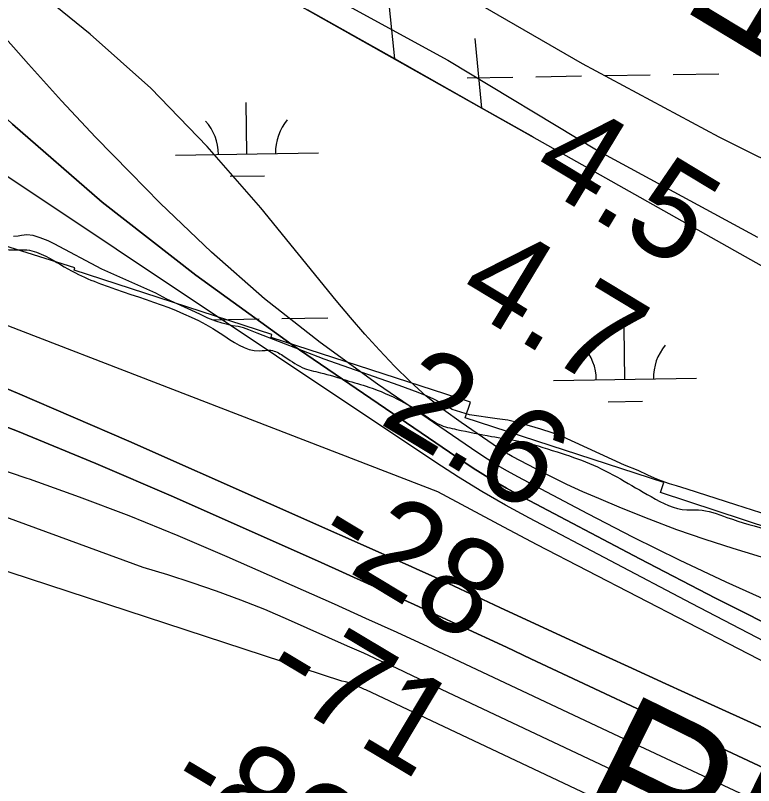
# Model space of a CAD drawing. Extents: x 3855477 to 3893699, y 299188 to 325115.
# Drawn here: x 3861858 to 3862374, y 316616 to 317154 of the extents above; entities that cross this region are included whole.
import ezdxf

# ---------------------------------------------------------------- set-up
doc = ezdxf.new("R2010")
doc.units = 0
for name, color, linetype in [('V-LEVE-TOET', 7, 'Continuous'), ('V-RIVR-EDGE', 7, 'Continuous'), ('V-RIVR-RANG', 7, 'Continuous'), ('V-RIVR-RANG-IDEN', 7, 'Continuous'), ('V-RRAP-FSHR', 7, 'Continuous'), ('V-RRAP-RVMT', 7, 'Continuous'), ('V-RRAP-RVMT-IDEN', 7, 'Continuous'), ('V-TOPO-DPTH', 7, 'Continuous'), ('V-TOPO-MAJR', 7, 'Continuous'), ('V-TOPO-MINR', 7, 'Continuous'), ('V-TOPO-WATR', 7, 'Continuous'), ('V-WETL-SWMP', 7, 'Continuous')]:
    doc.layers.add(name, color=color, linetype=linetype)

msp = doc.modelspace()

# ---------------------------------------------------------------- linework, layer by layer
at = {"layer": 'V-LEVE-TOET'}
msp.add_lwpolyline([(3862463.67, 317012.4), (3862350.14, 317069.05), (3862254.51, 317120.23), (3862173.11, 317167.56), (3862088, 317214.94), (3861990.29, 317268.78), (3861903.02, 317310.89), (3861809.48, 317359.41), (3861689.68, 317422.99), (3861660.73, 317434.38), (3861643.33, 317437.2), (3861632.74, 317435.2), (3861627.38, 317427.86), (3861628.86, 317417.8), (3861638.31, 317411.37), (3861673.53, 317394.62), (3861732.44, 317368.66), (3861791.2, 317328.42), (3861854.71, 317288.67), (3861937.17, 317241.33), (3862060.15, 317177.71), (3862160.49, 317122.79), (3862265.5, 317059.36), (3862376.89, 316999.04)], dxfattribs=at)
at = {"layer": 'V-RIVR-EDGE'}
msp.add_spline([(3861643.53, 317089.49), (3861674.18, 317073.47), (3861698.46, 317060.26), (3861723.94, 317049.04), (3861744.63, 317038.63), (3861771.7, 317026.2), (3861804.75, 317012.17), (3861824.65, 317002.96), (3861840.97, 316994.15), (3861856.1, 316990.13), (3861866.47, 316990.1), (3861879.61, 316985.69), (3861900.3, 316974.08), (3861917.82, 316966.46), (3862001.43, 316931.98), (3862028.89, 316919.56), (3862036.87, 316919.94), (3862045.23, 316916.33), (3862058.76, 316907.93), (3862071.5, 316904.31), (3862089.42, 316899.08), (3862105.35, 316894.26), (3862127.64, 316884.64), (3862144.36, 316874.64), (3862154.31, 316868.24), (3862166.65, 316864.62), (3862190.95, 316859.78), (3862210.07, 316856.54), (3862236.75, 316848.9), (3862259.45, 316840.88), (3862302.44, 316817.65), (3862327.52, 316808.43), (3862335.49, 316808.41), (3862355.41, 316803.18), (3862386.07, 316793.93), (3862408.77, 316787.5), (3862429.48, 316781.07), (3862460.14, 316771.43), (3862476.86, 316765.01), (3862487.22, 316762.2), (3862505.52, 316751), (3862525.42, 316737.4), (3862548.5, 316722.99), (3862579.14, 316706.58)], degree=3, dxfattribs=at)
at = {"layer": 'V-RRAP-FSHR'}
for p, q in [((3862123.35, 317123.63), (3862118.6, 317172.23)), ((3862184.31, 317089.24), (3862179.57, 317137.84))]:
    msp.add_line(p, q, dxfattribs=at)
for points in [[(3863755.9, 316222.32), (3863272.86, 316481.96), (3862847.86, 316733.36), (3862473.5, 316926.11), (3861935.6, 317229.54), (3861789.61, 317312.68)], [(3862123.35, 317123.63), (3862062.38, 317158.03)], [(3862184.31, 317089.24), (3862123.35, 317123.63)], [(3862220.4, 317068.89), (3862184.31, 317089.24)]]:
    msp.add_lwpolyline(points, dxfattribs=at)
at = {"layer": 'V-RRAP-RVMT'}
for p, q in [((3861899.98, 316977.66), (3861761.13, 317021.23)), ((3861899.44, 316975.94), (3861899.98, 316977.66)), ((3862037.61, 316931.1), (3861899.44, 316975.94)), ((3862037.13, 316929.01), (3862037.61, 316931.1)), ((3862176.41, 316883.79), (3862037.13, 316929.01)), ((3862172.53, 316872.81), (3862176.41, 316883.79)), ((3862311.31, 316827.52), (3862172.53, 316872.81)), ((3862309, 316820.54), (3862311.31, 316827.52)), ((3862440.97, 316777.01), (3862309, 316820.54))]:
    msp.add_line(p, q, dxfattribs=at)
at = {"layer": 'V-TOPO-DPTH'}
for points in [[(3862398.61, 316693.2), (3862222.96, 316784.06), (3862199.72, 316796.23), (3862176.56, 316808.56), (3862153.53, 316821.11), (3861655.23, 317013.53), (3861624.19, 317026.54), (3861537.43, 317064.64), (3861514.09, 317075), (3861490.8, 317085.47), (3861467.59, 317096.11), (3861444.43, 317106.87), (3861362.07, 317145.5), (3861309.75, 317169.79), (3861257.31, 317193.81), (3861204.69, 317217.42), (3861151.94, 317240.76), (3861099.14, 317263.99), (3861046.39, 317287.34), (3860993.73, 317310.87), (3860941.12, 317334.53), (3860934.1, 317337.7), (3860878.1, 317363.14)], [(3862398.61, 316693.2), (3862222.96, 316784.06), (3862199.72, 316796.23), (3862176.56, 316808.56), (3862153.53, 316821.11), (3861655.23, 317013.53), (3861624.19, 317026.54), (3861537.43, 317064.64), (3861514.09, 317075), (3861490.8, 317085.47), (3861467.59, 317096.11), (3861444.43, 317106.87), (3861362.07, 317145.5), (3861309.75, 317169.79), (3861257.31, 317193.81), (3861204.69, 317217.42), (3861151.94, 317240.76), (3861099.14, 317263.99), (3861046.39, 317287.34), (3860993.73, 317310.87), (3860941.12, 317334.53), (3860934.1, 317337.7), (3860878.1, 317363.14)], [(3861660.87, 317267.4), (3861795.55, 317134.72), (3861856.32, 317077.98), (3861918.97, 317023.54), (3861984.44, 316972.52), (3862051.79, 316923.78), (3862166.81, 316845.16), (3862178.19, 316837.66), (3862189.73, 316830.43), (3862201.51, 316823.6), (3862213.45, 316817.03), (3862294.67, 316774.12), (3862347.54, 316746.73), (3862400.7, 316719.9)], [(3861660.87, 317267.4), (3861795.55, 317134.72), (3861856.32, 317077.98), (3861918.97, 317023.54), (3861984.44, 316972.52), (3862051.79, 316923.78), (3862166.81, 316845.16), (3862178.19, 316837.66), (3862189.73, 316830.43), (3862201.51, 316823.6), (3862213.45, 316817.03), (3862294.67, 316774.12), (3862347.54, 316746.73), (3862400.7, 316719.9)], [(3862452.8, 316752.91), (3862359.91, 316781.36), (3862340.14, 316787.74), (3862320.52, 316794.51), (3862301.1, 316801.86), (3862281.83, 316809.6), (3862265.91, 316816.28), (3862254.77, 316821.12), (3862243.73, 316826.16), (3862232.82, 316831.5), (3862222.01, 316837.03), (3862205.43, 316845.79), (3862203, 316847.13), (3862200.6, 316848.52), (3862198.25, 316849.99), (3862195.93, 316851.52), (3862169.75, 316869.41), (3862157.4, 316878.42), (3862145.46, 316887.91), (3862134.12, 316898.12), (3862123.18, 316908.81), (3862112.69, 316919.98), (3862102.4, 316931.32), (3862092.39, 316942.92), (3862082.57, 316954.68), (3862029.81, 317019.5), (3861992.32, 317062.3), (3861952.93, 317103.14), (3861910.69, 317141.02), (3861866.55, 317176.93)], [(3861466.28, 317043.19), (3861624.34, 316984.23), (3861703.33, 316953.94), (3861781.92, 316922.7), (3861859.94, 316890.04), (3861937.56, 316856.42), (3862132.84, 316769.74), (3862140.89, 316766.13), (3862148.93, 316762.49), (3862156.94, 316758.8), (3862164.94, 316755.07), (3862172.93, 316751.32), (3862180.92, 316747.58), (3862188.92, 316743.86), (3862196.92, 316740.15), (3862233.64, 316723.15), (3862260.02, 316710.97), (3862286.42, 316698.83), (3862312.84, 316686.75), (3862339.28, 316674.71), (3862633.23, 316541.24)], [(3862633.23, 316541.24), (3862339.28, 316674.71), (3862312.84, 316686.75), (3862286.42, 316698.83), (3862260.02, 316710.97), (3862233.64, 316723.15), (3862196.92, 316740.15), (3862188.92, 316743.86), (3862180.92, 316747.58), (3862172.93, 316751.32), (3862164.94, 316755.07), (3862156.94, 316758.8), (3862148.93, 316762.49), (3862140.89, 316766.13), (3862132.84, 316769.74), (3861937.56, 316856.42), (3861859.94, 316890.04), (3861781.92, 316922.7), (3861703.33, 316953.94), (3861624.34, 316984.23), (3861466.28, 317043.19)], [(3861543.74, 316977.42), (3861562.28, 316970.2), (3861581.02, 316963.52), (3861599.89, 316957.2), (3861618.82, 316951.05), (3861637.72, 316944.77), (3861656.54, 316938.3), (3861675.33, 316931.69), (3861749.26, 316905.27), (3861804.73, 316884.74), (3861859.87, 316863.39), (3861914.52, 316840.81), (3861968.85, 316817.41), (3862071.98, 316771.61), (3862104.46, 316757.06), (3862136.88, 316742.37), (3862169.2, 316727.46), (3862201.45, 316712.42), (3862218.51, 316704.39), (3862259.25, 316685.24), (3862300, 316666.11), (3862340.76, 316647), (3862381.53, 316627.91)], [(3862381.53, 316627.91), (3862340.76, 316647), (3862300, 316666.11), (3862259.25, 316685.24), (3862218.51, 316704.39), (3862201.45, 316712.42), (3862169.2, 316727.46), (3862136.88, 316742.37), (3862104.46, 316757.06), (3862071.98, 316771.61), (3861968.85, 316817.41), (3861914.52, 316840.81), (3861859.87, 316863.39), (3861804.73, 316884.74), (3861749.26, 316905.27), (3861675.33, 316931.69), (3861656.54, 316938.3), (3861637.72, 316944.77), (3861618.82, 316951.05), (3861599.89, 316957.2), (3861581.02, 316963.52), (3861562.28, 316970.2), (3861543.74, 316977.42)]]:
    msp.add_lwpolyline(points, dxfattribs=at)
at = {"layer": 'V-TOPO-MAJR'}
msp.add_lwpolyline([(3862419.74, 316584.41), (3862346.04, 316618.92), (3862272.38, 316653.53), (3862168.61, 316702.42), (3862146.84, 316712.59), (3862125.02, 316722.66), (3862103.14, 316732.58), (3862081.22, 316742.41), (3862006.29, 316775.7), (3861972.18, 316790.31), (3861937.84, 316804.32), (3861903.14, 316817.4), (3861868.2, 316829.88), (3861866.7, 316830.39), (3861832.26, 316841.94), (3861797.73, 316853.19), (3861763.06, 316864.01), (3861728.29, 316874.55), (3861693.67, 316885.45), (3861659.33, 316897.13), (3861625.4, 316909.98), (3861591.76, 316923.6), (3861490.7, 316966.53)], dxfattribs=at)
at = {"layer": 'V-TOPO-MINR'}
for points in [[(3862398.61, 316693.2), (3862222.96, 316784.06), (3862199.72, 316796.23), (3862176.56, 316808.56), (3862153.53, 316821.11), (3861655.23, 317013.53), (3861624.19, 317026.54), (3861537.43, 317064.64), (3861514.09, 317075), (3861490.8, 317085.47), (3861467.59, 317096.11), (3861444.43, 317106.87), (3861362.07, 317145.5), (3861309.75, 317169.79), (3861257.31, 317193.81), (3861204.69, 317217.42), (3861151.94, 317240.76), (3861099.14, 317263.99), (3861046.39, 317287.34), (3860993.73, 317310.87), (3860941.12, 317334.53), (3860934.1, 317337.7), (3860878.1, 317363.14)], [(3862400.7, 316719.9), (3862347.54, 316746.73), (3862294.67, 316774.12), (3862213.45, 316817.03), (3862201.51, 316823.6), (3862189.73, 316830.43), (3862178.19, 316837.66), (3862166.81, 316845.16), (3862051.79, 316923.78), (3861984.44, 316972.52), (3861918.97, 317023.54), (3861856.32, 317077.98), (3861795.55, 317134.72), (3861660.87, 317267.4)], [(3862404.48, 316704.59), (3862330.72, 316742.86), (3862217.46, 316802.66), (3862200.75, 316811.81), (3862184.24, 316821.3), (3862168.03, 316831.3), (3862152.02, 316841.63), (3861817.27, 317065.08), (3861776.98, 317092.35), (3861736.94, 317119.97), (3861697.25, 317148.1), (3861657.8, 317176.57), (3861597.14, 317220.95), (3861588.02, 317227.18), (3861578.66, 317232.99), (3861568.95, 317238.17), (3861558.99, 317242.94)], [(3862387.54, 316743.16), (3862354.86, 316757.94), (3862322.4, 316773.18), (3862290.28, 316789.13), (3862258.38, 316805.55), (3862209.44, 316831.41), (3862202.26, 316835.36), (3862195.17, 316839.48), (3862188.22, 316843.83), (3862181.37, 316848.34), (3862111.27, 316896.26), (3862071.22, 316925.36), (3862032.4, 316955.91), (3861995.39, 316988.65), (3861959.6, 317022.84), (3861938.53, 317044.16), (3861914.45, 317069.03), (3861890.7, 317094.22), (3861867.47, 317119.88), (3861844.58, 317145.86), (3861821.2, 317171.27)], [(3862585.42, 316454.74), (3862103.1, 316682.52), (3862102.24, 316682.93), (3862100.5, 316683.73), (3862096.31, 316685.59), (3862093.92, 316686.57), (3862091.47, 316687.41), (3862088.98, 316688.12), (3862086.46, 316688.68), (3861390.39, 316916.73), (3861368.99, 316926.77), (3861347.62, 316936.86), (3861256.15, 316980.28), (3861194.89, 317009.08), (3861133.49, 317037.6), (3861071.9, 317065.67), (3861010.16, 317093.45), (3860959.67, 317115.96), (3860922.94, 317131.92), (3860886.02, 317147.42)], [(3862633.23, 316541.24), (3862339.28, 316674.71), (3862312.84, 316686.75), (3862286.42, 316698.83), (3862260.02, 316710.97), (3862233.64, 316723.15), (3862196.92, 316740.15), (3862188.92, 316743.86), (3862180.92, 316747.58), (3862172.93, 316751.32), (3862164.94, 316755.07), (3862156.94, 316758.8), (3862148.93, 316762.49), (3862140.89, 316766.13), (3862132.84, 316769.74), (3861937.56, 316856.42), (3861859.94, 316890.04), (3861781.92, 316922.7), (3861703.33, 316953.94), (3861624.34, 316984.23), (3861466.28, 317043.19)], [(3862381.53, 316627.91), (3862340.76, 316647), (3862300, 316666.11), (3862259.25, 316685.24), (3862218.51, 316704.39), (3862201.45, 316712.42), (3862169.2, 316727.46), (3862136.88, 316742.37), (3862104.46, 316757.06), (3862071.98, 316771.61), (3861968.85, 316817.41), (3861914.52, 316840.81), (3861859.87, 316863.39), (3861804.73, 316884.74), (3861749.26, 316905.27), (3861675.33, 316931.69), (3861656.54, 316938.3), (3861637.72, 316944.77), (3861618.82, 316951.05), (3861599.89, 316957.2), (3861581.02, 316963.52), (3861562.28, 316970.2), (3861543.74, 316977.42)], [(3862398.57, 316568.53), (3862135.83, 316692.45), (3862124.52, 316697.74), (3862113.19, 316702.98), (3862101.82, 316708.14), (3862090.43, 316713.25), (3862049.1, 316731.62), (3862032.54, 316738.68), (3862015.86, 316745.39), (3861998.98, 316751.58), (3861981.96, 316757.44), (3861964.81, 316762.9), (3861947.61, 316768.2), (3861434.58, 316956.09)]]:
    msp.add_lwpolyline(points, dxfattribs=at)
at = {"layer": 'V-TOPO-WATR'}
msp.add_lwpolyline([(3862452.8, 316752.91), (3862359.91, 316781.36), (3862340.14, 316787.74), (3862320.52, 316794.51), (3862301.1, 316801.86), (3862281.83, 316809.6), (3862265.91, 316816.28), (3862254.77, 316821.12), (3862243.73, 316826.16), (3862232.82, 316831.5), (3862222.01, 316837.03), (3862205.43, 316845.79), (3862203, 316847.13), (3862200.6, 316848.52), (3862198.25, 316849.99), (3862195.93, 316851.52), (3862169.75, 316869.41), (3862157.4, 316878.42), (3862145.46, 316887.91), (3862134.12, 316898.12), (3862123.18, 316908.81), (3862112.69, 316919.98), (3862102.4, 316931.32), (3862092.39, 316942.92), (3862082.57, 316954.68), (3862029.81, 317019.5), (3861992.32, 317062.3), (3861952.93, 317103.14), (3861910.69, 317141.02), (3861866.55, 317176.93)], dxfattribs=at)
at = {"layer": 'V-WETL-SWMP'}
for p, q in [((3862173.91, 317110.44), (3862205.91, 317110.96)), ((3862221.91, 317111.22), (3862253.9, 317111.74)), ((3862269.9, 317112), (3862301.9, 317112.52)), ((3862317.89, 317112.78), (3862349.89, 317113.3)), ((3862020.17, 317057.18), (3862019.58, 317093.18)), ((3861970.17, 317056.37), (3862070.16, 317058)), ((3862008.42, 317041.56), (3862032.42, 317041.95)), ((3861996.64, 316941.35), (3862028.64, 316941.87)), ((3862044.64, 316942.13), (3862076.63, 316942.66)), ((3862284.21, 316899.6), (3862283.62, 316935.6)), ((3862234.21, 316898.79), (3862334.2, 316900.42)), ((3862272.46, 316883.98), (3862296.46, 316884.37))]:
    msp.add_line(p, q, dxfattribs=at)
msp.add_lwpolyline([(3862431.64, 316789.63), (3862361.62, 316812.04), (3862327.57, 316822.95), (3862320.3, 316825.14), (3862315.33, 316826.72), (3862309.59, 316828.7), (3862304.81, 316830.67), (3862300.23, 316832.64), (3862293.54, 316835.97), (3862283.98, 316839.72), (3862240.81, 316859.54), (3862233.36, 316862.31), (3862225.52, 316864.89), (3862217.48, 316867.27), (3862210.01, 316869.27), (3862202.35, 316871.07), (3862194.88, 316872.11), (3862175.72, 316874.8), (3862163.47, 316878.58), (3862155.65, 316883.26), (3862150.69, 316885.81), (3862146.1, 316887.78), (3862139.79, 316890.34), (3862126.6, 316895.46), (3862074.2, 316913.66), (3862027.37, 316931.99), (3862021.45, 316934.36), (3862017.81, 316935.55), (3862013.98, 316936.55), (3862010.15, 316937.16), (3862002.88, 316938.97), (3861998.48, 316940.35), (3861992.74, 316942.53), (3861987.2, 316945.27), (3861981.66, 316947.82), (3861964.09, 316955.68), (3861956.45, 316959.79), (3861918.82, 316976.68), (3861885.6, 316994.49), (3861881.21, 316996.46), (3861875.67, 316998.63), (3861870.89, 317000.21), (3861866.48, 317000.64), (3861862.63, 317000.3), (3861860.32, 316999.74), (3861857.06, 316999.39)], dxfattribs=at)
for centre, start, end in [((3861964.92, 317056.76), 0.1615, 41.7052), ((3862075.4, 317058.56), 140.1615, 181.7052), ((3862228.96, 316899.18), 0.1615, 41.7052), ((3862339.43, 316900.98), 140.1615, 181.7052)]:
    msp.add_arc(centre, 35.25, start, end, dxfattribs=at)

# ---------------------------------------------------------------- texts
at = {"layer": 'V-RIVR-RANG'}
for s, rotation, p in [('4.5', 328.8683, (3862215.89, 317040.1)), ('4.7', 328.8683, (3862164.4, 316954.38)), ('2.6', 328.8683, (3862111.32, 316869.61)), ('-28', 328.8683, (3862064.34, 316781.16)), ('-71', 329.1469, (3862027.5, 316686.22)), ('-82', 329.1469, (3861961.28, 316609.29))]:
    msp.add_text(s, height=67, rotation=rotation, dxfattribs=at).set_placement(p)
at = {"layer": 'V-RIVR-RANG-IDEN'}
msp.add_text('R-23.9', height=83, rotation=58.8632, dxfattribs=at).set_placement((3862396.14, 317104.07))
at = {"layer": 'V-RRAP-RVMT-IDEN'}
msp.add_text('REVET.', height=100, rotation=333.8299, dxfattribs=at).set_placement((3862243.14, 316592.55))

doc.saveas('drawing.dxf')
